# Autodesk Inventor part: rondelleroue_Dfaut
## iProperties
Created: 2007-07
Part Number: rondelleroue_Dfaut
Document SubType Name: Modeling
Designer: EF
Density: 1 g/cm^3
Author: EF
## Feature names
1. Base1
